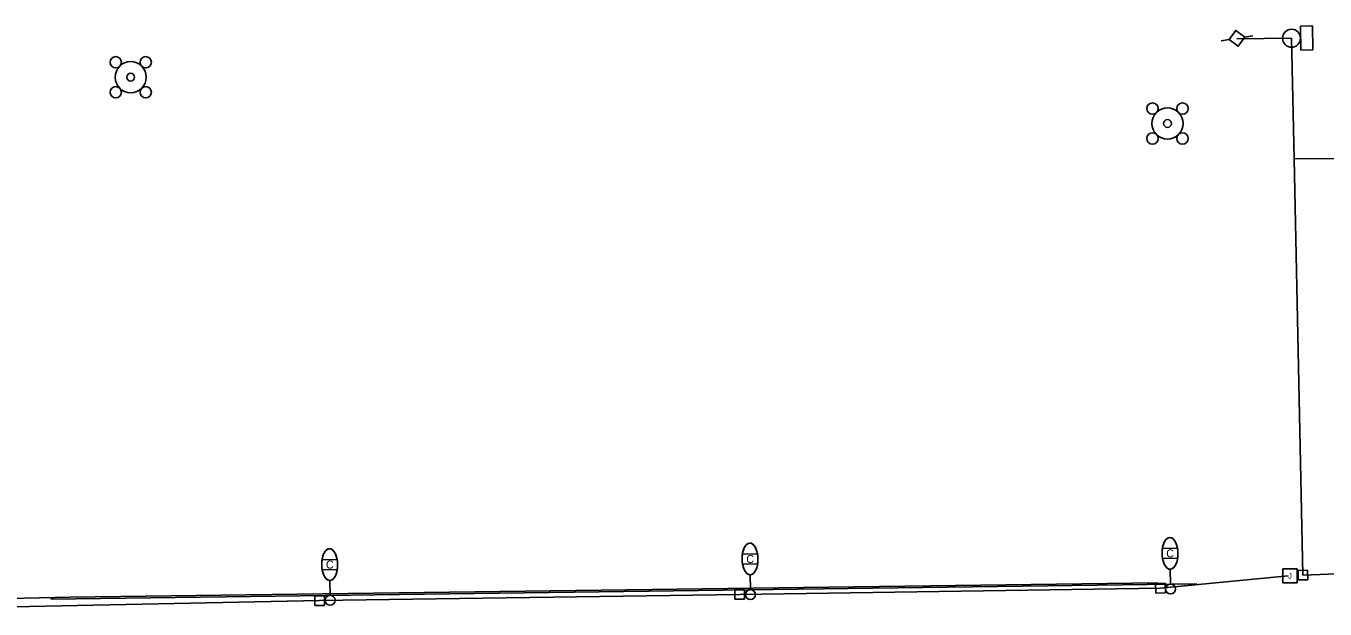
# Model space of a CAD drawing. Extents: x 915723 to 927758, y 636394 to 638609.
# Drawn here: x 921176 to 921825, y 636901 to 637192 of the extents above; entities that cross this region are included whole.
import ezdxf

# ---------------------------------------------------------------- set-up
doc = ezdxf.new("R2010")
doc.units = 0
for name, color, linetype in [('ConduitBM', 7, 'Continuous'), ('ConduitOT', 7, 'Continuous'), ('DrShaftConc', 7, 'Continuous'), ('LoadCenter', 7, 'Continuous'), ('Miscellaneous2', 7, 'Continuous'), ('PoleElec_ep', 7, 'Continuous'), ('PoleLight', 7, 'Continuous'), ('PoleLightHM_ep', 7, 'Continuous'), ('PullBox', 7, 'Continuous'), ('SchemElectricProp', 7, 'Continuous'), ('TextStructuresLabel', 7, 'Continuous')]:
    doc.layers.add(name, color=color, linetype=linetype)

msp = doc.modelspace()

# ---------------------------------------------------------------- linework, layer by layer
at = {"layer": 'ConduitBM'}
msp.add_line((921814.1, 636917.87), (921957.87, 636923.54), dxfattribs=at)
at = {"layer": 'ConduitOT'}
for p, q in [((921742.93, 636911.35), (921806.67, 636917.51)), ((921322.78, 636905.12), (921532.67, 636908.21)), ((921532.67, 636908.21), (921742.93, 636911.35)), ((921113.17, 636900.91), (921322.78, 636905.12))]:
    msp.add_line(p, q, dxfattribs=at)
at = {"layer": 'DrShaftConc'}
for p, q in [((921781.17, 637185.95), (921808.41, 637186.21)), ((921809.69, 637125.99), (921808.41, 637186.24)), ((921954.64, 637126.86), (921809.69, 637125.99)), ((921814.1, 636917.87), (921809.69, 637125.99)), ((921197.98, 636906.8), (921741.55, 636914.07))]:
    msp.add_line(p, q, dxfattribs=at)
msp.add_lwpolyline([(921167.71, 636906.11), (921197.98, 636906.8)], dxfattribs=at)
at = {"layer": 'LoadCenter'}
for p, q in [((921812.83, 637192.3), (921818.83, 637192.39)), ((921812.99, 637180.31), (921812.83, 637192.3)), ((921818.83, 637192.39), (921818.99, 637180.39)), ((921818.99, 637180.39), (921812.99, 637180.31))]:
    msp.add_line(p, q, dxfattribs=at)
msp.add_circle((921808.41, 637186.24), 4.5, dxfattribs=at)
at = {"layer": 'Miscellaneous2'}
for p, q in [((921541.56, 636928.49), (921534.05, 636928.39)), ((921541.56, 636928.49), (921541.56, 636928.49)), ((921751.43, 636931.29), (921743.92, 636931.19)), ((921751.43, 636931.29), (921751.43, 636931.29)), ((921331.52, 636925.67), (921324, 636925.57)), ((921324.07, 636920.57), (921331.58, 636920.67)), ((921331.52, 636925.67), (921331.52, 636925.67)), ((921331.58, 636920.67), (921331.58, 636920.67)), ((921534.11, 636923.39), (921541.63, 636923.49)), ((921541.63, 636923.49), (921541.63, 636923.49)), ((921743.99, 636926.19), (921751.5, 636926.29)), ((921751.5, 636926.29), (921751.5, 636926.29))]:
    msp.add_line(p, q, dxfattribs=at)
for centre, start_param, end_param in [((921537.84, 636925.94), 4.391271, 5.033538), ((921537.84, 636925.94), 4.391241, 4.391271), ((921537.84, 636925.94), 1.249648, 1.891946), ((921747.71, 636928.74), 4.391271, 5.033538), ((921747.71, 636928.74), 4.391241, 4.391271), ((921747.71, 636928.74), 1.249648, 1.891946), ((921327.79, 636923.12), 4.391271, 5.033538), ((921327.79, 636923.12), 4.391241, 4.391271), ((921327.79, 636923.12), 1.249648, 1.891946)]:
    msp.add_ellipse(centre, major_axis=(0.11, -7.92), ratio=0.5, start_param=start_param, end_param=end_param, dxfattribs=at)
at = {"layer": 'PoleElec_ep'}
for p, q in [((921789.14, 637187.47), (921785.14, 637186.84)), ((921773.21, 637184.98), (921777.21, 637185.6))]:
    msp.add_line(p, q, dxfattribs=at)
msp.add_lwpolyline([(921785.14, 637186.84), (921780.56, 637190.19), (921777.21, 637185.6), (921781.8, 637182.25), (921785.14, 637186.84)], dxfattribs=at)
at = {"layer": 'PoleLight'}
for p, q in [((921534.05, 636928.39), (921541.56, 636928.49)), ((921743.92, 636931.19), (921751.43, 636931.29)), ((921324, 636925.57), (921331.52, 636925.67)), ((921331.58, 636920.67), (921324.07, 636920.57)), ((921541.63, 636923.49), (921534.11, 636923.39)), ((921751.5, 636926.29), (921743.99, 636926.19)), ((921747.92, 636913.4), (921747.82, 636920.82)), ((921328, 636907.78), (921327.9, 636915.2)), ((921538.04, 636910.6), (921537.94, 636918.02))]:
    msp.add_line(p, q, dxfattribs=at)
for centre in [(921328.03, 636905.3), (921328.03, 636905.3), (921538.07, 636908.12), (921538.07, 636908.12), (921747.95, 636910.92), (921747.95, 636910.92)]:
    msp.add_circle(centre, 2.48, dxfattribs=at)
for centre in [(921537.84, 636925.94), (921747.71, 636928.74), (921327.79, 636923.12)]:
    msp.add_ellipse(centre, major_axis=(0.11, -7.92), ratio=0.5, dxfattribs=at)
for centre, start_param, end_param in [((921537.84, 636925.94), 1.891945, 4.391241), ((921747.71, 636928.74), 1.891945, 4.391241), ((921327.79, 636923.12), 1.891945, 4.391241), ((921327.79, 636923.12), 5.033538, 6.283185), ((921327.79, 636923.12), 0.847605, 1.249648), ((921537.84, 636925.94), 5.033538, 6.283185), ((921537.84, 636925.94), 0, 0.847605), ((921537.84, 636925.94), 0.847605, 1.249648), ((921747.71, 636928.74), 5.033538, 6.283185), ((921747.71, 636928.74), 0, 0.847605), ((921747.71, 636928.74), 0.847605, 1.249648), ((921327.79, 636923.12), 0, 0.847605)]:
    msp.add_ellipse(centre, major_axis=(0.11, -7.92), ratio=0.5, start_param=start_param, end_param=end_param, dxfattribs=at)
at = {"layer": 'PoleLightHM_ep'}
for centre, radius in [((921220.88, 637174.25), 2.81), ((921228.37, 637166.76), 7.79), ((921235.87, 637174.25), 2.81), ((921228.37, 637166.76), 1.95), ((921220.88, 637159.26), 2.81), ((921235.87, 637159.26), 2.81), ((921738.95, 637151.12), 2.81), ((921746.44, 637143.62), 7.79), ((921753.94, 637151.12), 2.81), ((921746.44, 637143.62), 1.95), ((921738.95, 637136.13), 2.81), ((921753.94, 637136.13), 2.81)]:
    msp.add_circle(centre, radius, dxfattribs=at)
at = {"layer": 'PullBox'}
for p, q in [((921804.08, 636921.08), (921811.2, 636921.08)), ((921804.08, 636913.95), (921804.08, 636921.08)), ((921811.2, 636921.08), (921811.2, 636913.95)), ((921811.66, 636920.23), (921816.46, 636920.31)), ((921811.74, 636915.43), (921811.66, 636920.23)), ((921816.54, 636915.51), (921811.74, 636915.43)), ((921816.46, 636920.31), (921816.54, 636915.51)), ((921320.33, 636907.48), (921325.14, 636907.56)), ((921325.14, 636907.56), (921325.22, 636902.76)), ((921530.23, 636910.57), (921535.03, 636910.65)), ((921530.31, 636905.77), (921530.23, 636910.57)), ((921535.03, 636910.65), (921535.11, 636905.85)), ((921740.49, 636913.71), (921745.29, 636913.79)), ((921740.57, 636908.9), (921740.49, 636913.71)), ((921745.38, 636908.99), (921740.57, 636908.9)), ((921745.29, 636913.79), (921745.38, 636908.99)), ((921811.2, 636913.95), (921804.08, 636913.95)), ((921320.42, 636902.68), (921320.33, 636907.48)), ((921325.22, 636902.76), (921320.42, 636902.68)), ((921535.11, 636905.85), (921530.31, 636905.77))]:
    msp.add_line(p, q, dxfattribs=at)
at = {"layer": 'SchemElectricProp'}
msp.add_line((921188.54, 636905.92), (921761.17, 636913.58), dxfattribs=at)

# ---------------------------------------------------------------- texts
at = {"layer": 'ConduitOT'}
msp.add_text('J', height=2.85, dxfattribs=at).set_placement((921806.67, 636916.09))
at = {"layer": 'TextStructuresLabel'}
for p in [(921535.99, 636923.92), (921745.86, 636926.71), (921325.95, 636921.1)]:
    msp.add_text('C', height=4, rotation=0.76701, dxfattribs=at).set_placement(p)

doc.saveas('drawing.dxf')
